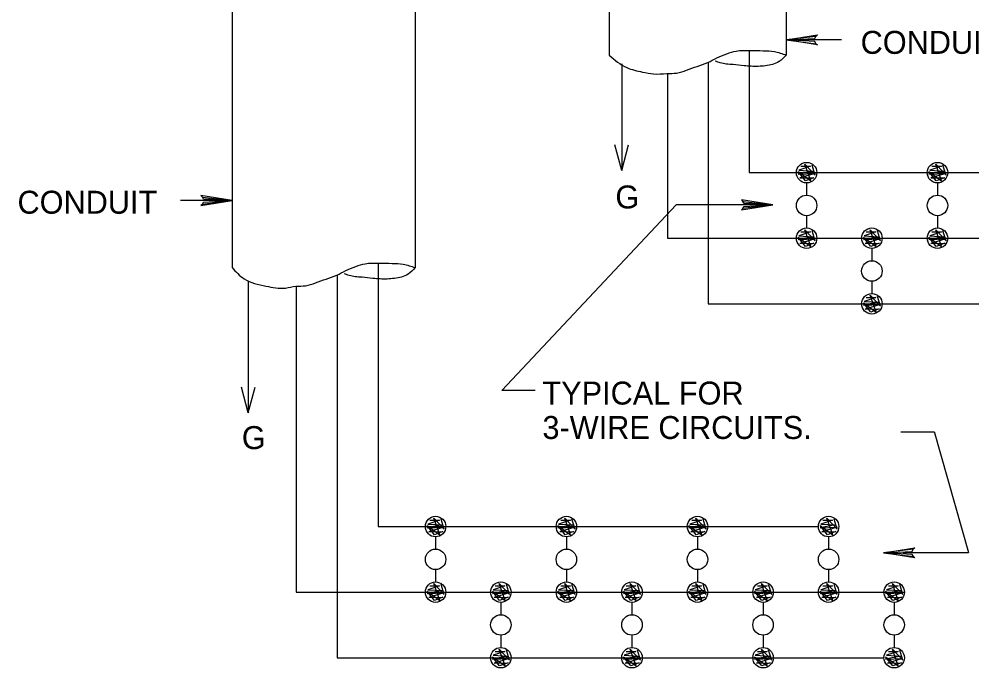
# Model space of a CAD drawing. Extents: x 638448 to 639352, y 297825 to 299013.
# Drawn here: x 639063.8 to 639203.3, y 298653.6 to 298748.6 of the extents above; entities that cross this region are included whole.
import ezdxf

# ---------------------------------------------------------------- set-up
doc = ezdxf.new("R2010")
doc.units = 0
for name, color, linetype in [('1', 7, 'Continuous'), ('2', 7, 'Continuous'), ('3', 7, 'Continuous')]:
    doc.layers.add(name, color=color, linetype=linetype)

msp = doc.modelspace()

# ---------------------------------------------------------------- linework, layer by layer
at = {"layer": '1'}
for p, q in [((639152.03, 298726.46), (639151.03, 298730.21)), ((639152.03, 298726.46), (639153.03, 298730.21)), ((639097.32, 298690.98), (639096.32, 298694.73)), ((639097.32, 298690.98), (639098.32, 298694.73))]:
    msp.add_line(p, q, dxfattribs=at)
at = {"layer": '2'}
for p, q in [((639094.97, 298750.62), (639094.97, 298712.22)), ((639121.76, 298750.62), (639121.76, 298712.22)), ((639150.16, 298750.62), (639150.16, 298743.35)), ((639176.1, 298750.62), (639176.1, 298743.35)), ((639170.7, 298744.01), (639170.7, 298726.13)), ((639152.03, 298742.04), (639152.03, 298726.46)), ((639164.7, 298742.29), (639164.7, 298706.93)), ((639158.7, 298740.63), (639158.7, 298716.53)), ((639179.68, 298727.06), (639177.96, 298726.47)), ((639178.27, 298727.06), (639179.68, 298727.06)), ((639179.71, 298724.91), (639178.86, 298727.37)), ((639178.86, 298727.37), (639180.36, 298725.77)), ((639180.36, 298725.77), (639179.91, 298727.22)), ((639198.84, 298727.06), (639197.12, 298726.47)), ((639197.43, 298727.06), (639198.84, 298727.06)), ((639198.87, 298724.91), (639198.02, 298727.37)), ((639198.02, 298727.37), (639199.52, 298725.77)), ((639199.52, 298725.77), (639199.07, 298727.22)), ((639170.7, 298726.13), (639235.16, 298726.13)), ((639180.07, 298726.35), (639177.85, 298725.93)), ((639178.92, 298724.91), (639177.85, 298726.28)), ((639177.85, 298726.28), (639179.71, 298724.91)), ((639177.85, 298725.93), (639180.33, 298726.02)), ((639177.96, 298726.47), (639180.07, 298726.35)), ((639180.33, 298726.02), (639178.12, 298725.35)), ((639178.12, 298725.35), (639180.16, 298725.39)), ((639180.16, 298725.39), (639178.92, 298724.91)), ((639179.1, 298726.13), (639179.1, 298726.13)), ((639179.1, 298726.13), (639179.1, 298726.13)), ((639199.23, 298726.35), (639197.01, 298725.93)), ((639198.08, 298724.91), (639197.01, 298726.28)), ((639197.01, 298726.28), (639198.87, 298724.91)), ((639197.01, 298725.93), (639199.49, 298726.02)), ((639197.12, 298726.47), (639199.23, 298726.35)), ((639199.49, 298726.02), (639197.28, 298725.35)), ((639197.28, 298725.35), (639199.32, 298725.39)), ((639199.32, 298725.39), (639198.08, 298724.91)), ((639198.26, 298726.13), (639198.26, 298726.13)), ((639198.26, 298726.13), (639198.26, 298726.13)), ((639179.1, 298724.63), (639179.1, 298722.83)), ((639198.26, 298724.63), (639198.26, 298722.83)), ((639160.01, 298721.41), (639134.47, 298694.22)), ((639174.13, 298721.41), (639160.01, 298721.41)), ((639179.1, 298719.83), (639179.1, 298718.03)), ((639198.26, 298719.83), (639198.26, 298718.03)), ((639179.68, 298717.46), (639177.96, 298716.87)), ((639177.96, 298716.87), (639180.07, 298716.75)), ((639178.27, 298717.46), (639179.68, 298717.46)), ((639179.71, 298715.31), (639178.86, 298717.77)), ((639178.86, 298717.77), (639180.36, 298716.17)), ((639180.36, 298716.17), (639179.91, 298717.62)), ((639189.24, 298717.46), (639187.52, 298716.87)), ((639187.52, 298716.87), (639189.63, 298716.75)), ((639187.83, 298717.46), (639189.24, 298717.46)), ((639189.27, 298715.31), (639188.42, 298717.77)), ((639188.42, 298717.77), (639189.92, 298716.17)), ((639189.92, 298716.17), (639189.47, 298717.62)), ((639198.84, 298717.46), (639197.12, 298716.87)), ((639197.12, 298716.87), (639199.23, 298716.75)), ((639197.43, 298717.46), (639198.84, 298717.46)), ((639198.87, 298715.31), (639198.02, 298717.77)), ((639198.02, 298717.77), (639199.52, 298716.17)), ((639199.52, 298716.17), (639199.07, 298717.62)), ((639158.7, 298716.53), (639247.76, 298716.53)), ((639180.07, 298716.75), (639177.85, 298716.33)), ((639178.92, 298715.31), (639177.85, 298716.68)), ((639177.85, 298716.68), (639179.71, 298715.31)), ((639177.85, 298716.33), (639180.33, 298716.42)), ((639180.33, 298716.42), (639178.12, 298715.75)), ((639178.12, 298715.75), (639180.16, 298715.79)), ((639180.16, 298715.79), (639178.92, 298715.31)), ((639179.06, 298716.62), (639179.06, 298716.62)), ((639179.1, 298716.53), (639179.1, 298716.53)), ((639179.1, 298716.53), (639179.1, 298716.53)), ((639189.63, 298716.75), (639187.41, 298716.33)), ((639188.48, 298715.31), (639187.41, 298716.68)), ((639187.41, 298716.68), (639189.27, 298715.31)), ((639187.41, 298716.33), (639189.89, 298716.42)), ((639189.89, 298716.42), (639187.68, 298715.75)), ((639187.68, 298715.75), (639189.72, 298715.79)), ((639189.72, 298715.79), (639188.48, 298715.31)), ((639188.66, 298716.53), (639188.66, 298716.53)), ((639188.66, 298716.53), (639188.66, 298716.53)), ((639188.66, 298716.53), (639188.66, 298716.53)), ((639199.23, 298716.75), (639197.01, 298716.33)), ((639198.08, 298715.31), (639197.01, 298716.68)), ((639197.01, 298716.68), (639198.87, 298715.31)), ((639197.01, 298716.33), (639199.49, 298716.42)), ((639199.49, 298716.42), (639197.28, 298715.75)), ((639197.28, 298715.75), (639199.32, 298715.79)), ((639199.32, 298715.79), (639198.08, 298715.31)), ((639198.22, 298716.62), (639198.22, 298716.62)), ((639198.26, 298716.53), (639198.26, 298716.53)), ((639198.26, 298716.53), (639198.26, 298716.53)), ((639198.26, 298716.53), (639198.26, 298716.53)), ((639188.66, 298715.03), (639188.66, 298713.23)), ((639116.36, 298712.88), (639116.36, 298674.32)), ((639097.32, 298710.17), (639097.32, 298690.98)), ((639110.36, 298711.16), (639110.36, 298655.12)), ((639188.66, 298710.23), (639188.66, 298708.43)), ((639104.36, 298709.5), (639104.36, 298664.72)), ((639189.63, 298707.15), (639187.41, 298706.73)), ((639189.24, 298707.86), (639187.52, 298707.27)), ((639187.52, 298707.27), (639189.63, 298707.15)), ((639187.83, 298707.86), (639189.24, 298707.86)), ((639189.27, 298705.71), (639188.42, 298708.17)), ((639188.42, 298708.17), (639189.92, 298706.57)), ((639189.92, 298706.57), (639189.47, 298708.02)), ((639164.7, 298706.93), (639247.76, 298706.93)), ((639188.48, 298705.71), (639187.41, 298707.08)), ((639187.41, 298707.08), (639189.27, 298705.71)), ((639187.41, 298706.73), (639189.89, 298706.82)), ((639189.89, 298706.82), (639187.68, 298706.15)), ((639187.68, 298706.15), (639189.72, 298706.19)), ((639189.72, 298706.19), (639188.48, 298705.71)), ((639188.62, 298707.02), (639188.62, 298707.02)), ((639188.66, 298706.93), (639188.66, 298706.93)), ((639188.66, 298706.93), (639188.66, 298706.93)), ((639188.66, 298706.93), (639188.66, 298706.93)), ((639188.66, 298706.93), (639188.66, 298706.93)), ((639188.66, 298706.93), (639188.66, 298706.93)), ((639139.32, 298694.22), (639134.47, 298694.22)), ((639197.74, 298688.16), (639192.89, 298688.16)), ((639197.76, 298688.24), (639202.83, 298670.5)), ((639125.34, 298675.25), (639123.62, 298674.67)), ((639123.93, 298675.25), (639125.34, 298675.25)), ((639125.37, 298673.11), (639124.52, 298675.57)), ((639124.52, 298675.57), (639126.02, 298673.96)), ((639126.02, 298673.96), (639125.57, 298675.42)), ((639144.5, 298675.25), (639142.78, 298674.67)), ((639143.09, 298675.25), (639144.5, 298675.25)), ((639144.53, 298673.11), (639143.68, 298675.57)), ((639143.68, 298675.57), (639145.18, 298673.96)), ((639145.18, 298673.96), (639144.73, 298675.42)), ((639163.7, 298675.25), (639161.98, 298674.67)), ((639162.29, 298675.25), (639163.7, 298675.25)), ((639163.73, 298673.11), (639162.88, 298675.57)), ((639162.88, 298675.57), (639164.38, 298673.96)), ((639164.38, 298673.96), (639163.93, 298675.42)), ((639182.9, 298675.25), (639181.18, 298674.67)), ((639181.49, 298675.25), (639182.9, 298675.25)), ((639182.93, 298673.11), (639182.08, 298675.57)), ((639182.08, 298675.57), (639183.58, 298673.96)), ((639183.58, 298673.96), (639183.13, 298675.42)), ((639116.36, 298674.32), (639180.82, 298674.32)), ((639125.73, 298674.55), (639123.51, 298674.13)), ((639124.58, 298673.11), (639123.51, 298674.47)), ((639123.51, 298674.47), (639125.37, 298673.11)), ((639123.51, 298674.13), (639125.99, 298674.22)), ((639123.62, 298674.67), (639125.73, 298674.55)), ((639125.99, 298674.22), (639123.78, 298673.54)), ((639124.76, 298674.32), (639124.76, 298674.32)), ((639124.76, 298674.32), (639124.76, 298674.32)), ((639144.89, 298674.55), (639142.67, 298674.13)), ((639143.74, 298673.11), (639142.67, 298674.47)), ((639142.67, 298674.47), (639144.53, 298673.11)), ((639142.67, 298674.13), (639145.15, 298674.22)), ((639142.78, 298674.67), (639144.89, 298674.55)), ((639145.15, 298674.22), (639142.94, 298673.54)), ((639143.92, 298674.32), (639143.92, 298674.32)), ((639143.92, 298674.32), (639143.92, 298674.32)), ((639164.09, 298674.55), (639161.87, 298674.13)), ((639162.94, 298673.11), (639161.87, 298674.47)), ((639161.87, 298674.47), (639163.73, 298673.11)), ((639161.87, 298674.13), (639164.35, 298674.22)), ((639161.98, 298674.67), (639164.09, 298674.55)), ((639164.35, 298674.22), (639162.14, 298673.54)), ((639163.12, 298674.32), (639163.12, 298674.32)), ((639163.12, 298674.32), (639163.12, 298674.32)), ((639183.29, 298674.55), (639181.07, 298674.13)), ((639182.14, 298673.11), (639181.07, 298674.47)), ((639181.07, 298674.47), (639182.93, 298673.11)), ((639181.07, 298674.13), (639183.55, 298674.22)), ((639181.18, 298674.67), (639183.29, 298674.55)), ((639183.55, 298674.22), (639181.34, 298673.54)), ((639182.32, 298674.32), (639182.32, 298674.32)), ((639182.32, 298674.32), (639182.32, 298674.32)), ((639123.78, 298673.54), (639125.82, 298673.59)), ((639125.82, 298673.59), (639124.58, 298673.11)), ((639124.76, 298672.82), (639124.76, 298671.02)), ((639142.94, 298673.54), (639144.98, 298673.59)), ((639144.98, 298673.59), (639143.74, 298673.11)), ((639143.92, 298672.82), (639143.92, 298671.02)), ((639162.14, 298673.54), (639164.18, 298673.59)), ((639164.18, 298673.59), (639162.94, 298673.11)), ((639163.12, 298672.82), (639163.12, 298671.02)), ((639181.34, 298673.54), (639183.38, 298673.59)), ((639183.38, 298673.59), (639182.14, 298673.11)), ((639182.32, 298672.82), (639182.32, 298671.02)), ((639202.83, 298670.46), (639193.23, 298670.46)), ((639124.76, 298668.02), (639124.76, 298666.22)), ((639143.92, 298668.02), (639143.92, 298666.22)), ((639163.12, 298668.02), (639163.12, 298666.22)), ((639182.32, 298668.02), (639182.32, 298666.22)), ((639125.34, 298665.65), (639123.62, 298665.07)), ((639123.93, 298665.65), (639125.34, 298665.65)), ((639125.37, 298663.51), (639124.52, 298665.97)), ((639124.52, 298665.97), (639126.02, 298664.36)), ((639126.02, 298664.36), (639125.57, 298665.82)), ((639134.9, 298665.65), (639133.18, 298665.07)), ((639133.49, 298665.65), (639134.9, 298665.65)), ((639134.93, 298663.51), (639134.08, 298665.97)), ((639134.08, 298665.97), (639135.58, 298664.36)), ((639135.58, 298664.36), (639135.13, 298665.82)), ((639144.5, 298665.65), (639142.78, 298665.07)), ((639143.09, 298665.65), (639144.5, 298665.65)), ((639144.53, 298663.51), (639143.68, 298665.97)), ((639143.68, 298665.97), (639145.18, 298664.36)), ((639145.18, 298664.36), (639144.73, 298665.82)), ((639154.1, 298665.65), (639152.38, 298665.07)), ((639152.69, 298665.65), (639154.1, 298665.65)), ((639154.13, 298663.51), (639153.28, 298665.97)), ((639153.28, 298665.97), (639154.78, 298664.36)), ((639154.78, 298664.36), (639154.33, 298665.82)), ((639163.7, 298665.65), (639161.98, 298665.07)), ((639162.29, 298665.65), (639163.7, 298665.65)), ((639163.73, 298663.51), (639162.88, 298665.97)), ((639162.88, 298665.97), (639164.38, 298664.36)), ((639164.38, 298664.36), (639163.93, 298665.82)), ((639173.3, 298665.65), (639171.58, 298665.07)), ((639171.89, 298665.65), (639173.3, 298665.65)), ((639173.33, 298663.51), (639172.48, 298665.97)), ((639172.48, 298665.97), (639173.98, 298664.36)), ((639173.98, 298664.36), (639173.53, 298665.82)), ((639182.9, 298665.65), (639181.18, 298665.07)), ((639181.49, 298665.65), (639182.9, 298665.65)), ((639182.93, 298663.51), (639182.08, 298665.97)), ((639182.08, 298665.97), (639183.58, 298664.36)), ((639183.58, 298664.36), (639183.13, 298665.82)), ((639192.5, 298665.65), (639190.78, 298665.07)), ((639191.09, 298665.65), (639192.5, 298665.65)), ((639192.53, 298663.51), (639191.68, 298665.97)), ((639191.68, 298665.97), (639193.18, 298664.36)), ((639193.18, 298664.36), (639192.73, 298665.82)), ((639104.36, 298664.72), (639193.42, 298664.72)), ((639125.73, 298664.95), (639123.51, 298664.53)), ((639124.58, 298663.51), (639123.51, 298664.87)), ((639123.51, 298664.87), (639125.37, 298663.51)), ((639123.51, 298664.53), (639125.99, 298664.62)), ((639123.62, 298665.07), (639125.73, 298664.95)), ((639125.99, 298664.62), (639123.78, 298663.94)), ((639123.78, 298663.94), (639125.82, 298663.99)), ((639125.82, 298663.99), (639124.58, 298663.51)), ((639124.72, 298664.81), (639124.72, 298664.81)), ((639124.76, 298664.72), (639124.76, 298664.72)), ((639124.76, 298664.72), (639124.76, 298664.72)), ((639135.29, 298664.95), (639133.07, 298664.53)), ((639134.14, 298663.51), (639133.07, 298664.87)), ((639133.07, 298664.87), (639134.93, 298663.51)), ((639133.07, 298664.53), (639135.55, 298664.62)), ((639133.18, 298665.07), (639135.29, 298664.95)), ((639135.55, 298664.62), (639133.34, 298663.94)), ((639133.34, 298663.94), (639135.38, 298663.99)), ((639135.38, 298663.99), (639134.14, 298663.51)), ((639134.32, 298664.72), (639134.32, 298664.72)), ((639134.32, 298664.72), (639134.32, 298664.72)), ((639134.32, 298664.72), (639134.32, 298664.72)), ((639144.89, 298664.95), (639142.67, 298664.53)), ((639143.74, 298663.51), (639142.67, 298664.87)), ((639142.67, 298664.87), (639144.53, 298663.51)), ((639142.67, 298664.53), (639145.15, 298664.62)), ((639142.78, 298665.07), (639144.89, 298664.95)), ((639145.15, 298664.62), (639142.94, 298663.94)), ((639142.94, 298663.94), (639144.98, 298663.99)), ((639144.98, 298663.99), (639143.74, 298663.51)), ((639143.88, 298664.81), (639143.88, 298664.81)), ((639143.92, 298664.72), (639143.92, 298664.72)), ((639143.92, 298664.72), (639143.92, 298664.72)), ((639143.92, 298664.72), (639143.92, 298664.72)), ((639154.49, 298664.95), (639152.27, 298664.53)), ((639153.34, 298663.51), (639152.27, 298664.87)), ((639152.27, 298664.87), (639154.13, 298663.51)), ((639152.27, 298664.53), (639154.75, 298664.62)), ((639152.38, 298665.07), (639154.49, 298664.95)), ((639154.75, 298664.62), (639152.54, 298663.94)), ((639152.54, 298663.94), (639154.58, 298663.99)), ((639154.58, 298663.99), (639153.34, 298663.51)), ((639153.52, 298664.72), (639153.52, 298664.72)), ((639153.52, 298664.72), (639153.52, 298664.72)), ((639153.52, 298664.72), (639153.52, 298664.72)), ((639153.52, 298664.72), (639153.52, 298664.72)), ((639164.09, 298664.95), (639161.87, 298664.53)), ((639162.94, 298663.51), (639161.87, 298664.87)), ((639161.87, 298664.87), (639163.73, 298663.51)), ((639161.87, 298664.53), (639164.35, 298664.62)), ((639161.98, 298665.07), (639164.09, 298664.95)), ((639164.35, 298664.62), (639162.14, 298663.94)), ((639162.14, 298663.94), (639164.18, 298663.99)), ((639164.18, 298663.99), (639162.94, 298663.51)), ((639163.08, 298664.81), (639163.08, 298664.81)), ((639163.12, 298664.72), (639163.12, 298664.72)), ((639163.12, 298664.72), (639163.12, 298664.72)), ((639163.12, 298664.72), (639163.12, 298664.72)), ((639163.12, 298664.72), (639163.12, 298664.72)), ((639173.69, 298664.95), (639171.47, 298664.53)), ((639172.54, 298663.51), (639171.47, 298664.87)), ((639171.47, 298664.87), (639173.33, 298663.51)), ((639171.47, 298664.53), (639173.95, 298664.62)), ((639171.58, 298665.07), (639173.69, 298664.95)), ((639173.95, 298664.62), (639171.74, 298663.94)), ((639171.74, 298663.94), (639173.78, 298663.99)), ((639173.78, 298663.99), (639172.54, 298663.51)), ((639172.72, 298664.72), (639172.72, 298664.72)), ((639172.72, 298664.72), (639172.72, 298664.72)), ((639172.72, 298664.72), (639172.72, 298664.72)), ((639172.72, 298664.72), (639172.72, 298664.72)), ((639172.72, 298664.72), (639172.72, 298664.72)), ((639183.29, 298664.95), (639181.07, 298664.53)), ((639182.14, 298663.51), (639181.07, 298664.87)), ((639181.07, 298664.87), (639182.93, 298663.51)), ((639181.07, 298664.53), (639183.55, 298664.62)), ((639181.18, 298665.07), (639183.29, 298664.95)), ((639183.55, 298664.62), (639181.34, 298663.94)), ((639181.34, 298663.94), (639183.38, 298663.99)), ((639183.38, 298663.99), (639182.14, 298663.51)), ((639182.28, 298664.81), (639182.28, 298664.81)), ((639182.32, 298664.72), (639182.32, 298664.72)), ((639182.32, 298664.72), (639182.32, 298664.72)), ((639182.32, 298664.72), (639182.32, 298664.72)), ((639182.32, 298664.72), (639182.32, 298664.72)), ((639182.32, 298664.72), (639182.32, 298664.72)), ((639192.89, 298664.95), (639190.67, 298664.53)), ((639191.74, 298663.51), (639190.67, 298664.87)), ((639190.67, 298664.87), (639192.53, 298663.51)), ((639190.67, 298664.53), (639193.15, 298664.62)), ((639190.78, 298665.07), (639192.89, 298664.95)), ((639193.15, 298664.62), (639190.94, 298663.94)), ((639190.94, 298663.94), (639192.98, 298663.99)), ((639192.98, 298663.99), (639191.74, 298663.51)), ((639191.92, 298664.72), (639191.92, 298664.72)), ((639191.92, 298664.72), (639191.92, 298664.72)), ((639191.92, 298664.72), (639191.92, 298664.72)), ((639191.92, 298664.72), (639191.92, 298664.72)), ((639191.92, 298664.72), (639191.92, 298664.72)), ((639191.92, 298664.72), (639191.92, 298664.72)), ((639134.32, 298663.22), (639134.32, 298661.42)), ((639153.52, 298663.22), (639153.52, 298661.42)), ((639172.72, 298663.22), (639172.72, 298661.42)), ((639191.92, 298663.22), (639191.92, 298661.42)), ((639134.32, 298658.42), (639134.32, 298656.62)), ((639153.52, 298658.42), (639153.52, 298656.62)), ((639172.72, 298658.42), (639172.72, 298656.62)), ((639191.92, 298658.42), (639191.92, 298656.62)), ((639134.9, 298656.05), (639133.18, 298655.47)), ((639133.18, 298655.47), (639135.29, 298655.35)), ((639133.49, 298656.05), (639134.9, 298656.05)), ((639134.93, 298653.91), (639134.08, 298656.37)), ((639134.08, 298656.37), (639135.58, 298654.76)), ((639135.58, 298654.76), (639135.13, 298656.22)), ((639154.1, 298656.05), (639152.38, 298655.47)), ((639152.38, 298655.47), (639154.49, 298655.35)), ((639152.69, 298656.05), (639154.1, 298656.05)), ((639154.13, 298653.91), (639153.28, 298656.37)), ((639153.28, 298656.37), (639154.78, 298654.76)), ((639154.78, 298654.76), (639154.33, 298656.22)), ((639173.3, 298656.05), (639171.58, 298655.47)), ((639171.58, 298655.47), (639173.69, 298655.35)), ((639171.89, 298656.05), (639173.3, 298656.05)), ((639173.33, 298653.91), (639172.48, 298656.37)), ((639172.48, 298656.37), (639173.98, 298654.76)), ((639173.98, 298654.76), (639173.53, 298656.22)), ((639192.5, 298656.05), (639190.78, 298655.47)), ((639190.78, 298655.47), (639192.89, 298655.35)), ((639191.09, 298656.05), (639192.5, 298656.05)), ((639192.53, 298653.91), (639191.68, 298656.37)), ((639191.68, 298656.37), (639193.18, 298654.76)), ((639193.18, 298654.76), (639192.73, 298656.22)), ((639110.36, 298655.12), (639190.42, 298655.12)), ((639135.29, 298655.35), (639133.07, 298654.93)), ((639134.14, 298653.91), (639133.07, 298655.27)), ((639133.07, 298655.27), (639134.93, 298653.91)), ((639133.07, 298654.93), (639135.55, 298655.02)), ((639135.55, 298655.02), (639133.34, 298654.34)), ((639133.34, 298654.34), (639135.38, 298654.39)), ((639135.38, 298654.39), (639134.14, 298653.91)), ((639134.28, 298655.21), (639134.28, 298655.21)), ((639134.32, 298655.12), (639134.32, 298655.12)), ((639134.32, 298655.12), (639134.32, 298655.12)), ((639134.32, 298655.12), (639134.32, 298655.12)), ((639134.32, 298655.12), (639134.32, 298655.12)), ((639134.32, 298655.12), (639134.32, 298655.12)), ((639154.49, 298655.35), (639152.27, 298654.93)), ((639153.34, 298653.91), (639152.27, 298655.27)), ((639152.27, 298655.27), (639154.13, 298653.91)), ((639152.27, 298654.93), (639154.75, 298655.02)), ((639154.75, 298655.02), (639152.54, 298654.34)), ((639152.54, 298654.34), (639154.58, 298654.39)), ((639154.58, 298654.39), (639153.34, 298653.91)), ((639153.48, 298655.21), (639153.48, 298655.21)), ((639153.52, 298655.12), (639153.52, 298655.12)), ((639153.52, 298655.12), (639153.52, 298655.12)), ((639153.52, 298655.12), (639153.52, 298655.12)), ((639153.52, 298655.12), (639153.52, 298655.12)), ((639153.52, 298655.12), (639153.52, 298655.12)), ((639173.69, 298655.35), (639171.47, 298654.93)), ((639172.54, 298653.91), (639171.47, 298655.27)), ((639171.47, 298655.27), (639173.33, 298653.91)), ((639171.47, 298654.93), (639173.95, 298655.02)), ((639173.95, 298655.02), (639171.74, 298654.34)), ((639171.74, 298654.34), (639173.78, 298654.39)), ((639173.78, 298654.39), (639172.54, 298653.91)), ((639172.68, 298655.21), (639172.68, 298655.21)), ((639172.72, 298655.12), (639172.72, 298655.12)), ((639172.72, 298655.12), (639172.72, 298655.12)), ((639172.72, 298655.12), (639172.72, 298655.12)), ((639172.72, 298655.12), (639172.72, 298655.12)), ((639172.72, 298655.12), (639172.72, 298655.12)), ((639192.89, 298655.35), (639190.67, 298654.93)), ((639191.74, 298653.91), (639190.67, 298655.27)), ((639190.67, 298655.27), (639192.53, 298653.91)), ((639190.67, 298654.93), (639193.15, 298655.02)), ((639193.15, 298655.02), (639190.94, 298654.34)), ((639190.94, 298654.34), (639192.98, 298654.39)), ((639192.98, 298654.39), (639191.74, 298653.91)), ((639191.88, 298655.21), (639191.88, 298655.21)), ((639191.92, 298655.12), (639191.92, 298655.12)), ((639191.92, 298655.12), (639191.92, 298655.12)), ((639191.92, 298655.12), (639191.92, 298655.12)), ((639191.92, 298655.12), (639191.92, 298655.12)), ((639191.92, 298655.12), (639191.92, 298655.12))]:
    msp.add_line(p, q, dxfattribs=at)
for points in [[(639180.46, 298745.01), (639180.29, 298745.33), (639176.1, 298745.56), (639180.46, 298745.01), (639180.68, 298744.82), (639176.1, 298745.56), (639180.29, 298745.77), (639180.44, 298746.08), (639176.1, 298745.56), (639180.68, 298746.29), (639180.44, 298746.08)], [(639184.2, 298745.56), (639176.1, 298745.56)], [(639090.61, 298721.49), (639090.77, 298721.81), (639094.97, 298722.04), (639090.61, 298721.49), (639090.39, 298721.3), (639094.97, 298722.04), (639090.77, 298722.25), (639090.62, 298722.56), (639094.97, 298722.04), (639090.39, 298722.77), (639090.62, 298722.56)], [(639094.97, 298722.04), (639087.39, 298722.04)], [(639169.77, 298720.86), (639169.93, 298721.18), (639174.13, 298721.41), (639169.77, 298720.86), (639169.54, 298720.67), (639174.13, 298721.41), (639169.93, 298721.62), (639169.78, 298721.93), (639174.13, 298721.41), (639169.54, 298722.14), (639169.78, 298721.93)], [(639194.74, 298669.93), (639194.57, 298670.24), (639190.38, 298670.47), (639194.74, 298669.93), (639194.96, 298669.74), (639190.38, 298670.47), (639194.57, 298670.68), (639194.72, 298670.99), (639190.38, 298670.47), (639194.96, 298671.2), (639194.72, 298670.99)]]:
    msp.add_lwpolyline(points, dxfattribs=at)
for centre in [(639179.1, 298726.13), (639198.26, 298726.13), (639179.1, 298721.33), (639198.26, 298721.33), (639179.1, 298716.53), (639188.66, 298716.53), (639198.26, 298716.53), (639188.66, 298711.73), (639188.66, 298706.93), (639124.76, 298674.32), (639143.92, 298674.32), (639163.12, 298674.32), (639182.32, 298674.32), (639124.76, 298669.52), (639143.92, 298669.52), (639163.12, 298669.52), (639182.32, 298669.52), (639124.76, 298664.72), (639134.32, 298664.72), (639143.92, 298664.72), (639153.52, 298664.72), (639163.12, 298664.72), (639172.72, 298664.72), (639182.32, 298664.72), (639191.92, 298664.72), (639134.32, 298659.92), (639153.52, 298659.92), (639172.72, 298659.92), (639191.92, 298659.92), (639134.32, 298655.12), (639153.52, 298655.12), (639172.72, 298655.12), (639191.92, 298655.12)]:
    msp.add_circle(centre, 1.5, dxfattribs=at)
for points in [[(639150.16, 298743.35), (639152.78, 298741.51), (639155.06, 298740.86), (639156.69, 298740.58), (639158.64, 298740.63), (639160.06, 298740.71), (639161.53, 298741.12), (639163.08, 298741.69), (639164.63, 298742.26), (639165.93, 298742.92), (639167.4, 298743.53), (639168.79, 298743.93), (639170.79, 298744.02), (639172.74, 298743.98), (639174.37, 298743.85), (639176.1, 298743.35)], [(639176.1, 298743.35), (639175.07, 298742.39), (639173.07, 298741.77), (639172.01, 298741.69), (639169.93, 298741.77), (639168.34, 298741.94), (639167.32, 298742.02), (639166.46, 298742.22), (639165.69, 298742.43)], [(639094.97, 298712.23), (639096.71, 298710.59), (639099.92, 298709.52), (639102.77, 298709.24), (639104.3, 298709.5), (639105.72, 298709.58), (639107.19, 298709.99), (639108.74, 298710.56), (639110.29, 298711.13), (639111.59, 298711.79), (639113.06, 298712.4), (639114.45, 298712.8), (639116.45, 298712.89), (639118.4, 298712.85), (639120.03, 298712.72), (639121.76, 298712.22)], [(639121.76, 298712.22), (639120.73, 298711.26), (639118.73, 298710.64), (639117.67, 298710.56), (639115.59, 298710.64), (639114, 298710.81), (639112.98, 298710.89), (639112.12, 298711.09), (639111.35, 298711.3)]]:
    msp.add_spline(points, degree=3, dxfattribs=at)

# ---------------------------------------------------------------- texts
at = {"layer": '3'}
for s, p in [('CONDUIT', (639187.01, 298743.52)), ('G', (639151.09, 298720.89)), ('CONDUIT', (639063.53, 298720.12)), ('TYPICAL FOR', (639140.41, 298692.18)), ('3-WIRE CIRCUITS.', (639140.41, 298687.14)), ('G', (639096.38, 298685.66))]:
    msp.add_text(s, height=3.36, dxfattribs=at).set_placement(p)

doc.saveas('drawing.dxf')
